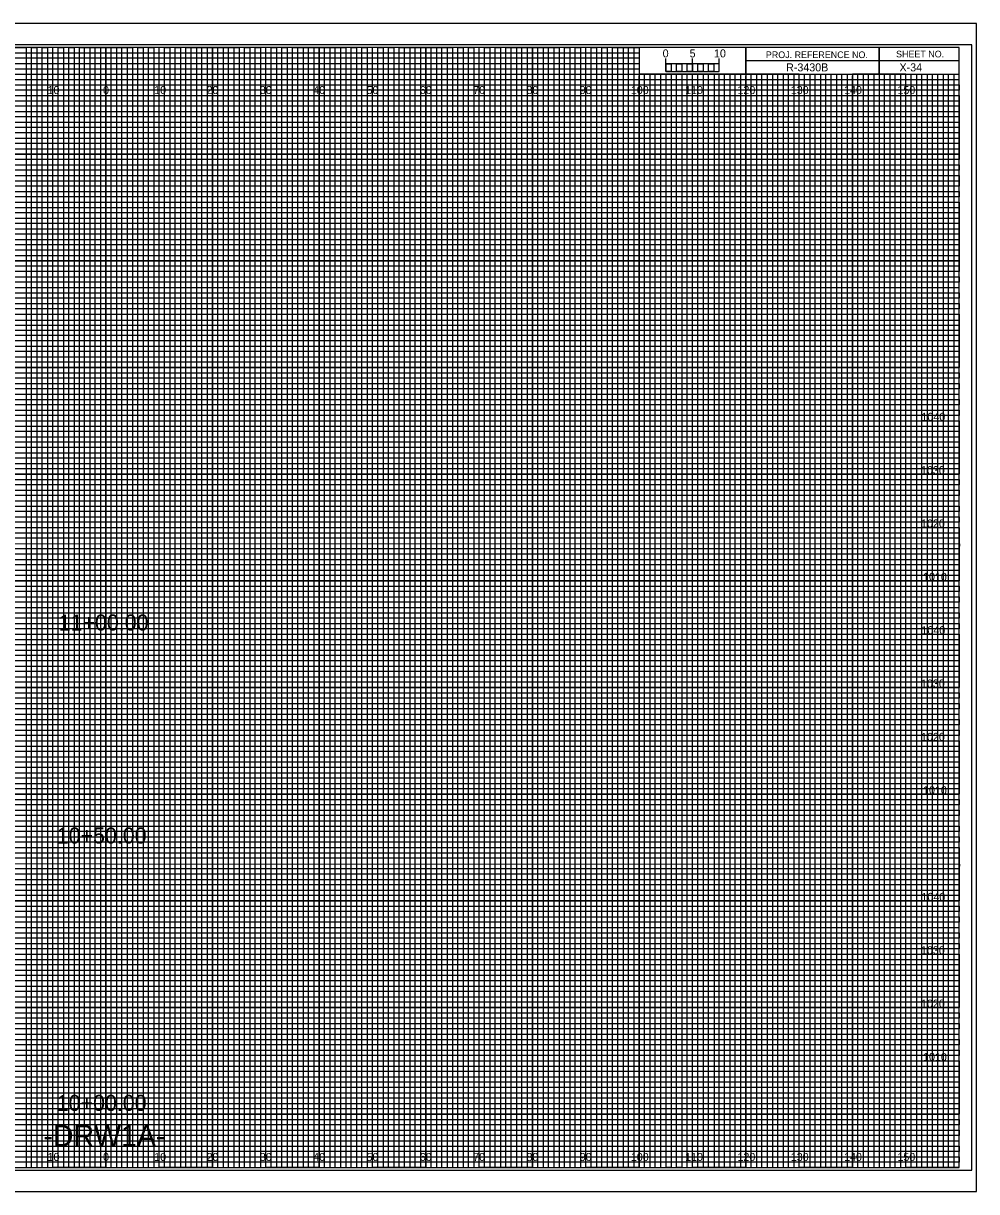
# Model space of a CAD drawing. Extents: x -13 to 323, y -5 to 215.
# Drawn here: x 144.5 to 323.3, y -4.5 to 214.5 of the extents above; entities that cross this region are included whole.
import ezdxf

# ---------------------------------------------------------------- set-up
doc = ezdxf.new("R2010")
doc.units = 0
for name, color, linetype in [('Prop XS Alignment Label', 7, 'Continuous'), ('Prop XS Bar Scale Labels', 7, 'Continuous'), ('Prop XS Elevation Labels', 7, 'Continuous'), ('Prop XS Offset Labels', 7, 'Continuous'), ('Prop XS Project Number', 7, 'Continuous'), ('Prop XS Sheet Number', 7, 'Continuous'), ('Prop XS Station Labels', 7, 'Continuous'), ('Sheet Cross Section CELL', 7, 'Continuous'), ('Sheet Cross Section Grid Major CELL', 7, 'Continuous'), ('Sheet Cross Section Grid Middle CELL', 7, 'Continuous'), ('Sheet Cross Section Grid Minor 1 CELL', 7, 'Continuous'), ('Sheet Cross Section Grid Minor 2 CELL', 7, 'Continuous'), ('Sheet Cross Section Scale CELL', 7, 'Continuous'), ('Sheet Cutting Line CELL', 7, 'Continuous'), ('Sheet DOT Grid CELL', 7, 'Continuous'), ('Sheet Plot Border Inside CELL', 7, 'Continuous'), ('Sheet Plot Border Outside CELL', 7, 'Continuous')]:
    doc.layers.add(name, color=color, linetype=linetype)

msp = doc.modelspace()

# ---------------------------------------------------------------- linework, layer by layer
at = {"layer": 'Sheet Cross Section CELL'}
for p, q in [((305, 210), (305, 205)), ((305, 205), (305, 210)), ((280, 207.5), (280, 205)), ((320, 207.49), (280, 207.49)), ((280, 205), (320, 205))]:
    msp.add_line(p, q, dxfattribs=at)
for points in [[(320, 210), (0, 210), (0, 0), (320, 0)], [(280, 210), (260, 210), (260, 205.03), (280, 205.03)], [(320, 210), (280, 210), (280, 205), (320, 205)]]:
    msp.add_lwpolyline(points, close=True, dxfattribs=at)
at = {"layer": 'Sheet Cross Section Grid Major CELL'}
for p, q in [((150, 210), (140, 210)), ((150, 0), (150, 210)), ((170, 210), (160, 210)), ((160, 210), (160, 0)), ((170, 0), (170, 210)), ((190, 210), (180, 210)), ((180, 210), (180, 0)), ((190, 0), (190, 210)), ((210, 210), (200, 210)), ((200, 210), (200, 0)), ((210, 0), (210, 210)), ((230, 210), (220, 210)), ((220, 210), (220, 0)), ((230, 0), (230, 210)), ((250, 210), (240, 210)), ((240, 210), (240, 0)), ((250, 0), (250, 210)), ((260, 210), (260, 0)), ((270, 0), (270, 205)), ((290, 205), (280, 205)), ((280, 205), (280, 0)), ((290, 0), (290, 205)), ((310, 205), (300, 205)), ((300, 205), (300, 0)), ((310, 0), (310, 205)), ((160, 0), (150, 0)), ((180, 0), (170, 0)), ((200, 0), (190, 0)), ((220, 0), (210, 0)), ((240, 0), (230, 0)), ((260, 0), (250, 0)), ((280, 0), (270, 0)), ((300, 0), (290, 0)), ((320, 0), (310, 0)), ((320, 0), (320, 0))]:
    msp.add_line(p, q, dxfattribs=at)
for points in [[(0, 200), (320, 200), (320, 190), (0, 190)], [(0, 180), (320, 180), (320, 170), (0, 170)], [(0, 160), (320, 160), (320, 150), (0, 150)], [(0, 140), (320, 140), (320, 130), (0, 130)], [(0, 120), (320, 120), (320, 110), (0, 110)], [(0, 100), (320, 100), (320, 90), (0, 90)], [(0, 80), (320, 80), (320, 70), (0, 70)], [(0, 60), (320, 60), (320, 50), (0, 50)], [(0, 40), (320, 40), (320, 30), (0, 30)], [(0, 20), (320, 20), (320, 10), (0, 10)]]:
    msp.add_lwpolyline(points, dxfattribs=at)
at = {"layer": 'Sheet Cross Section Grid Middle CELL'}
for points in [[(135, 210), (145, 210), (145, 0), (155, 0), (155, 210), (165, 210), (165, 0), (175, 0), (175, 210), (185, 210), (185, 0), (195, 0), (195, 210), (205, 210), (205, 0), (215, 0), (215, 210), (225, 210), (225, 0), (235, 0), (235, 210), (245, 210), (245, 0), (255, 0), (255, 210), (259.93, 210), (260, 210), (260, 205), (264.99, 205), (264.99, 0), (275, 0), (275, 205), (285, 205), (285, 0), (295, 0), (295, 205), (305, 205), (305, 0), (315, 0), (315, 205)], [(0, 205), (275, 205)], [(0, 185), (320, 185), (320, 195), (0, 195)], [(0, 165), (320, 165), (320, 175), (0, 175)], [(0, 145), (320, 145), (320, 155), (0, 155)], [(0, 125), (320, 125), (320, 135), (0, 135)], [(0, 105), (320, 105), (320, 115), (0, 115)], [(0, 85), (320, 85), (320, 95), (0, 95)], [(0, 65), (320, 65), (320, 75), (0, 75)], [(0, 45), (320, 45), (320, 55), (0, 55)], [(0, 25), (320, 25), (320, 35), (0, 35)], [(0, 5), (320, 5), (320, 15), (0, 15)]]:
    msp.add_lwpolyline(points, dxfattribs=at)
at = {"layer": 'Sheet Cross Section Grid Minor 1 CELL'}
for p, q in [((0, 209), (260, 209)), ((260, 209), (260, 207.98)), ((260, 207.98), (0, 207.98)), ((0, 207), (260, 207)), ((260, 205.89), (0, 205.89)), ((260, 207), (260, 205.89)), ((0, 204), (320, 204))]:
    msp.add_line(p, q, dxfattribs=at)
for points in [[(0, 203), (270, 203), (320, 203), (320, 202), (0, 202)], [(0, 201), (320, 201), (320, 199), (0, 199)], [(0, 198), (320, 198), (320, 197), (0, 196.98)], [(0, 196), (320, 196), (320, 194), (0, 194)], [(0, 193), (320, 193), (320, 192), (0, 192)], [(0, 191), (320, 191), (320, 189), (0, 189)], [(0, 188), (320, 188), (320, 187), (0, 187)], [(0, 186), (320, 186), (320, 184), (0, 184)], [(0, 183), (320, 183), (320, 182), (0, 182)], [(0, 181), (320, 181), (320, 179), (0, 179)], [(0, 178), (320, 178), (320, 177), (0, 177)], [(0, 176), (320, 176), (320, 173.95), (320, 173), (320, 172), (0, 172)], [(0, 174), (320, 174), (320, 173), (0, 173)], [(0, 171), (320, 171), (320, 169), (0, 169.03)], [(0, 169.03), (320, 169), (320, 168), (0, 168)], [(0, 167), (320, 167), (320, 166), (0, 166)], [(0, 164), (320, 164), (320, 163), (0, 163)], [(0, 162), (320, 162), (320, 161), (0, 161)], [(-0.07, 158.89), (320, 158.89), (320, 157.88), (-0.07, 157.88)], [(0, 157), (320, 157), (320, 156), (0, 156)], [(0, 154), (320, 154), (320, 153), (0, 153)], [(0, 152), (320, 152), (320, 151), (0, 151)], [(0, 149), (320, 149), (320, 148), (0, 148)], [(0, 147), (320, 147), (320, 146), (0, 146)], [(0, 144), (320, 144), (320, 143), (0, 143)], [(0, 142), (320, 142), (320, 141), (0, 141)], [(0, 139), (320, 139), (319.99, 137.98), (0, 138)], [(0, 137), (320, 137), (320, 136), (0, 136)], [(0, 134), (320, 134), (320, 133), (0, 133)], [(0, 132), (320, 132), (320, 131), (0, 131)], [(0, 129), (320, 129), (320, 128), (0, 128)], [(0, 127), (320, 127), (320, 126), (0, 126)], [(0, 124), (320, 124), (320, 123), (0, 123)], [(0, 122), (320, 122), (320, 121), (0, 121)], [(0, 119), (320, 119), (320, 118), (0, 118)], [(0, 116.99), (320.07, 116.91), (320, 116), (0, 116)], [(0, 114), (320, 114), (320, 113), (0, 113)], [(0, 112), (320, 112), (320, 111), (0, 111)], [(0, 109), (320, 109), (320, 108), (0, 108)], [(0, 107), (320, 107), (320, 106), (0, 106)], [(0, 104), (320, 104), (320, 103), (0, 103)], [(0, 102), (320, 102), (320, 101), (0, 101)], [(0, 99), (320, 99), (320, 98), (0, 98)], [(0, 97), (320, 97), (320, 96), (0, 96)], [(0, 94), (320, 94), (320, 93), (0, 93)], [(0, 92), (320, 92), (320, 91), (0, 91)], [(0, 89), (320, 89), (320, 88), (0, 88)], [(0, 87), (320, 87), (320, 86), (0, 86)], [(0, 84), (320, 84), (320, 83), (0, 83)], [(0, 82), (320, 82), (320, 81), (0, 81)], [(0, 79), (320, 79), (319.99, 77.98), (0, 78)], [(0, 77), (320, 77), (320, 76), (0, 76)], [(0, 74), (320, 74), (320, 73), (0, 73)], [(0, 72), (320, 72), (320, 71), (0, 71)], [(0, 69), (320, 69), (320, 68), (0, 68)], [(0, 67), (320, 67), (320, 66), (0, 66)], [(0, 64), (320, 64), (320, 63), (0, 63)], [(0, 62), (320, 62), (320, 61), (0, 61)], [(0, 59), (320, 59), (320, 58), (0, 58)], [(0, 56.99), (320.07, 56.91), (320, 56), (0, 56)], [(0, 54), (320, 54), (320, 53), (0, 53)], [(0, 52), (320, 52), (320, 51), (0, 51)], [(0, 49), (320, 49), (320, 48), (0, 48)], [(0, 47), (320, 47), (320, 46), (0, 46)], [(0, 44), (320, 44), (320, 43), (0, 43)], [(0, 42), (320, 42), (320, 41), (0, 41)], [(0, 39), (320, 39), (320, 38), (0, 38)], [(0, 37), (320, 37), (320, 36), (0, 36)], [(0, 34), (320, 34), (320, 33), (0, 33)], [(0, 32), (320, 32), (320, 31), (0, 31)], [(0, 29), (320, 29), (320, 28), (0, 28)], [(0, 27), (320, 27), (320, 26), (0, 26)], [(0, 24), (320, 24), (320, 23), (0, 23)], [(0, 22), (320, 22), (320, 21), (0, 21)], [(0, 19), (320, 19), (320, 18), (0, 18)], [(0, 17), (320, 17), (320, 16), (0, 16)], [(0, 14), (320, 14), (320, 13), (0, 13)], [(0, 12), (320, 12), (320, 11), (0, 11)], [(0, 9), (320, 9), (320, 8), (0, 8)], [(0, 7), (320, 7), (320, 6), (0, 6)], [(0, 4), (320, 4), (320, 3), (0, 3)], [(0, 2), (320, 2), (320, 1), (0, 1)]]:
    msp.add_lwpolyline(points, dxfattribs=at)
at = {"layer": 'Sheet Cross Section Grid Minor 2 CELL'}
for p, q in [((267, 205), (266.01, 205)), ((266.01, 205), (266.01, 0)), ((267, 0), (267, 205)), ((269, 205), (268, 205)), ((268, 205), (268, 0)), ((269, 0), (269, 205)), ((266.01, 0), (265, 0)), ((268, 0), (267, 0))]:
    msp.add_line(p, q, dxfattribs=at)
for points in [[(145, 0), (146, 0), (146, 210), (147, 210), (147, 0)], [(147, 0), (148, 0), (148, 210), (149, 210), (149, 0)], [(150, 0), (151, 0), (151, 210), (152, 210), (152, 0)], [(152, 0), (153, 0), (153, 210), (154, 210), (154, 0)], [(155, 0), (156, 0), (156, 210), (157, 210), (157, 0)], [(157, 0), (158, 0), (158, 210), (159, 210), (159, 0)], [(160, 0), (161, 0), (161, 210), (162, 210), (162, 0)], [(162, 0), (163, 0), (163, 210), (164, 210), (164, 0)], [(165, 0), (166, 0), (166, 210), (167, 210), (167, 0)], [(167, 0), (168, 0), (168, 210), (169, 210), (169, 0)], [(170, 0), (171, 0), (171, 210), (172, 210), (172, 0)], [(172, 0), (173, 0), (173, 210), (174, 210), (174, 0)], [(175, 0), (176, 0), (176, 210), (177, 210), (177, 0)], [(177, 0), (178, 0), (178, 210), (179, 210), (179, 0)], [(180, 0), (181, 0), (181, 210), (182, 210), (182, 0)], [(182, 0), (183, 0), (183, 210), (184, 210), (184, 0)], [(185, 0), (186, 0), (186, 210), (187, 210), (187, 0)], [(187, 0), (188, 0), (188, 210), (189, 210), (189, 0)], [(190, 0), (191, 0), (191, 210), (192, 210), (192, 0)], [(192, 0), (193, 0), (193, 210), (194, 210), (194, 0)], [(195, 0), (196, 0), (196, 210), (197, 210), (197, 0)], [(197, 0), (198, 0), (198, 210), (199, 210), (199, 0)], [(200, 0), (201, 0), (201, 210), (202, 210), (202, 0)], [(202, 0), (203, 0), (203, 210), (204, 210), (204, 0)], [(205, 0), (206, 0), (206, 210), (207, 210), (207, 0)], [(207, 0), (208, 0), (208, 210), (209, 210), (209, 0)], [(210, 0), (211, 0), (211, 210), (212, 210), (212, 0)], [(212, 0), (213, 0), (213, 210), (214, 210), (214, 0)], [(215, 0), (216, 0), (216, 210), (217, 210), (217, 0)], [(217, 0), (218, 0), (218, 210), (219, 210), (219, 0)], [(220, 0), (221, 0), (221, 210), (222, 210), (222, 0)], [(222, 0), (223, 0), (223, 210), (224, 210), (224, 0)], [(225, 0), (226, 0), (226, 210), (227, 210), (227, 0)], [(227, 0), (228, 0), (228, 210), (229, 210), (229, 0)], [(230, 0), (231, 0), (231, 210), (232, 210), (232, 0)], [(232, 0), (233, 0), (233, 210), (234, 210), (234, 0)], [(235, 0), (236, 0), (236, 210), (237, 210), (237, 0)], [(237, 0), (238, 0), (238, 210), (239, 210), (239, 0)], [(240, 0), (241, 0), (241, 210), (242, 210), (242, 0)], [(242, 0), (243, 0), (243, 210), (244, 210), (244, 0)], [(245, 0), (246, 0), (246, 210), (247, 210), (247, 0)], [(247, 0), (248, 0), (248, 210), (249, 210), (249, 0)], [(250, 0), (251, 0), (251, 210), (252, 210), (252, 0)], [(252, 0), (253, 0), (253, 210), (254, 210), (254, 0)], [(255, 0), (256, 0), (256, 210), (257, 210), (257, 0)], [(257, 0), (258, 0), (258, 210), (259, 210), (259, 0)], [(260, 0), (261, 0), (261, 205), (262.02, 205), (262.02, 0)], [(262, 0), (263, 0), (263, 205), (263.99, 205), (263.99, 0)], [(270, 0), (270.98, 0), (270.98, 205), (272, 205), (272, 0)], [(272, 0), (273, 0), (273, 205), (274.05, 205), (274.05, 0)], [(275, 0), (276, 0), (276, 205), (277, 205), (277, 0)], [(277, 0), (278, 0), (278, 205), (279, 205), (279, 0)], [(280, 0), (281, 0), (281, 205), (282, 205), (282, 0)], [(282, 0), (283, 0), (283, 205), (284, 205), (284, 0)], [(285, 0), (286, 0), (286, 205), (287, 205), (287, 0)], [(287, 0), (288, 0), (288, 205), (289, 205), (289, 0)], [(290, 0), (291, 0), (291, 205), (292, 205), (292, 0)], [(292, 0), (293, 0), (293, 205), (294, 205), (294, 0)], [(295, 0), (296, 0), (296, 205), (297, 205), (297, 0)], [(297, 0), (298, 0), (298, 205), (299, 205), (299, 0)], [(300, 0), (301, 0), (301, 205), (302, 205), (302, 0)], [(302, 0), (303, 0), (303, 205), (304, 205), (304, 0)], [(305, 0), (306, 0), (306, 205), (307, 205), (307, 0)], [(307, 0), (308, 0), (308, 205), (309, 205), (309, 0)], [(310, 0), (311, 0), (311, 205), (312, 205), (312, 0)], [(312, 0), (313, 0), (313, 205), (314, 205), (314, 0)], [(315, 0), (316, 0), (316, 205), (317, 205), (317, 0)], [(317, 0), (318, 0), (318, 205), (319, 205), (319, 0)]]:
    msp.add_lwpolyline(points, dxfattribs=at)
at = {"layer": 'Sheet Cross Section Scale CELL'}
for p, q in [((265, 205.49), (265, 207.9)), ((265, 206.9), (265, 207.9)), ((270, 205.49), (270, 207.9)), ((275, 205.49), (275, 207.9)), ((275, 206.9), (275, 207.9))]:
    msp.add_line(p, q, dxfattribs=at)
for points in [[(275, 206.9), (265, 206.9), (265, 205.49), (275, 205.49)], [(265, 206.9), (266, 206.9), (266, 205.49), (265, 205.49)], [(267, 206.9), (268, 206.9), (268, 205.49), (267, 205.49)], [(269, 206.9), (270, 206.9), (270, 205.49), (269, 205.49)], [(271, 206.9), (272, 206.9), (272, 205.49), (271, 205.49)], [(273, 206.9), (274, 206.9), (274, 205.49), (273, 205.49)]]:
    msp.add_lwpolyline(points, close=True, dxfattribs=at)
at = {"layer": 'Sheet Cutting Line CELL'}
for p, q in [((323.3, 214.5), (-13.4, 214.5)), ((-13.4, -4.5), (323.3, -4.5))]:
    msp.add_line(p, q, dxfattribs=at)
at = {"layer": 'Sheet DOT Grid CELL'}
for p, q in [((150, 0), (150, 210)), ((160, 0), (160, 210)), ((170, 0), (170, 210)), ((180, 0), (180, 210)), ((190, 0), (190, 210)), ((200, 0), (200, 210)), ((210, 0), (210, 210)), ((220, 0), (220, 210)), ((230, 0), (230, 210)), ((240, 0), (240, 210)), ((250, 0), (250, 210)), ((260, 0), (260, 204.69)), ((270, 0), (270, 204.69)), ((280, 0), (280, 204.69)), ((290, 0), (290, 204.69)), ((300, 0), (300, 204.69)), ((310, 0), (310, 204.69)), ((0, 200), (320, 200)), ((0, 190), (320, 190)), ((0, 180), (320, 180)), ((0, 170), (320, 170)), ((0, 160), (320, 160)), ((0, 150), (320, 150)), ((0, 140), (320, 140)), ((0, 130), (320, 130)), ((0, 120), (320, 120)), ((0, 110), (320, 110)), ((0, 100), (320, 100)), ((0, 90), (320, 90)), ((0, 80), (320, 80)), ((0, 70), (320, 70)), ((0, 60), (320, 60)), ((0, 50), (320, 50)), ((0, 40), (320, 40)), ((0, 30), (320, 30)), ((0, 20), (320, 20)), ((0, 10), (320, 10))]:
    msp.add_line(p, q, dxfattribs=at)
at = {"layer": 'Sheet Plot Border Inside CELL'}
msp.add_lwpolyline([(-10.8, -0.5), (322.4, -0.5), (322.4, 210.5), (-10.8, 210.5)], close=True, dxfattribs=at)
at = {"layer": 'Sheet Plot Border Outside CELL'}
msp.add_lwpolyline([(-13.4, -4.5), (323.3, -4.5), (323.3, 214.5), (-13.4, 214.5)], close=True, dxfattribs=at)

# ---------------------------------------------------------------- texts
at = {"layer": 'Prop XS Alignment Label'}
msp.add_text('-DRW1A-', height=4, dxfattribs=at).set_placement((148.26, 4))
at = {"layer": 'Prop XS Bar Scale Labels'}
for s, p in [('5', (269.47, 208.12)), ('10', (274.04, 208.12))]:
    msp.add_text(s, height=1.5, dxfattribs=at).set_placement(p)
at = {"layer": 'Prop XS Elevation Labels'}
for s, p in [('1040', (312.95, 140)), ('1030', (312.86, 130)), ('1020', (312.87, 120)), ('1010', (313.25, 110)), ('1040', (312.95, 100)), ('1030', (312.86, 90)), ('1020', (312.87, 80)), ('1010', (313.25, 70)), ('1040', (312.95, 50)), ('1030', (312.86, 40)), ('1020', (312.87, 30)), ('1010', (313.25, 20))]:
    msp.add_text(s, height=1.5, dxfattribs=at).set_placement(p)
at = {"layer": 'Prop XS Offset Labels'}
for s, p in [('10', (149.04, 201.25)), ('0', (159.45, 201.25)), ('0', (159.45, 201.25)), ('10', (169.04, 201.25)), ('20', (178.86, 201.25)), ('30', (188.86, 201.25)), ('40', (198.86, 201.25)), ('50', (208.86, 201.25)), ('60', (218.86, 201.25)), ('70', (228.86, 201.25)), ('80', (238.86, 201.25)), ('90', (248.86, 201.25)), ('100', (258.44, 201.25)), ('110', (268.62, 201.25)), ('120', (278.44, 201.25)), ('130', (288.44, 201.25)), ('140', (298.44, 201.25)), ('150', (308.44, 201.25)), ('10', (149.04, 1.25)), ('0', (159.45, 1.25)), ('0', (159.45, 1.25)), ('10', (169.04, 1.25)), ('20', (178.86, 1.25)), ('30', (188.86, 1.25)), ('40', (198.86, 1.25)), ('50', (208.86, 1.25)), ('60', (218.86, 1.25)), ('70', (228.86, 1.25)), ('80', (238.86, 1.25)), ('90', (248.86, 1.25)), ('100', (258.44, 1.25)), ('110', (268.62, 1.25)), ('120', (278.44, 1.25)), ('130', (288.44, 1.25)), ('140', (298.44, 1.25)), ('150', (308.44, 1.25))]:
    msp.add_text(s, height=1.5, dxfattribs=at).set_placement(p)
at = {"layer": 'Prop XS Project Number'}
msp.add_text('R-3430B', height=1.5, dxfattribs=at).set_placement((287.56, 205.5))
at = {"layer": 'Prop XS Sheet Number'}
msp.add_text('X-34', height=1.5, dxfattribs=at).set_placement((308.83, 205.5))
at = {"layer": 'Prop XS Station Labels'}
for s, p in [('11+00.00', (151.13, 100.68)), ('10+50.00', (150.77, 60.76)), ('10+00.00', (150.77, 10.63))]:
    msp.add_text(s, height=3, dxfattribs=at).set_placement(p)
at = {"layer": 'Sheet Cross Section CELL'}
for s, p in [('PROJ. REFERENCE NO.', (283.77, 207.99)), ('SHEET NO.', (308.19, 208.12))]:
    msp.add_text(s, height=1.25, dxfattribs=at).set_placement(p)
at = {"layer": 'Sheet Cross Section Scale CELL'}
msp.add_text('0', height=1.5, dxfattribs=at).set_placement((264.41, 208.12))

doc.saveas('drawing.dxf')
